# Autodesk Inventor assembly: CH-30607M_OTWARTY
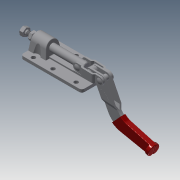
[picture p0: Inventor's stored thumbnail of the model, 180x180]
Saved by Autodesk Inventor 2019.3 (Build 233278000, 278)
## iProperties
Company: Î¢ÈíÖÐ¹ú
Created: 2012-09
Part Number: CH-30607M_OTWARTY
Material: Ogólny
Description: STEP AP203
Document SubType Name: Assembly
Designer: CADENGINEERING4
Sending System: SolidWorks 2010
Preprocessor: SwSTEP 2.0
Title: CH-30607M.STEP
Author: Î¢ÈíÓÃ»§
Revision Number: ÈÎºÎ
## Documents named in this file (10)
- D:\Vault_2016\Projekty\STRONA\Push-pull clamp\CH-30607M\CH-30607M_OTWARTY.iam
- D:\Vault_2016\Projekty\STRONA\Push-pull clamp\CH-30607M\CH-30607-01 BASE.ipt
- D:\Vault_2016\Projekty\STRONA\Push-pull clamp\CH-30607M\M8 Nut.ipt
- D:\Vault_2016\Projekty\STRONA\Push-pull clamp\CH-30607M\CH-SA-085012 SPINDLE SUPPLIED.ipt
- D:\Vault_2016\Projekty\STRONA\Push-pull clamp\CH-30607M\CH-30607-07.ipt
- D:\Vault_2016\Projekty\STRONA\Push-pull clamp\CH-30607M\CH-30607-05.ipt
- D:\Vault_2016\Projekty\STRONA\Push-pull clamp\CH-30607M\CH-30607-04 CONNECTING-PLATE.ipt
- D:\Vault_2016\Projekty\STRONA\Push-pull clamp\CH-30607M\CH-30607-06.ipt
- D:\Vault_2016\Projekty\STRONA\Push-pull clamp\CH-30607M\CH-30607-03 HANDLE.ipt
- D:\Vault_2016\Projekty\STRONA\Push-pull clamp\CH-30607M\CH-30607-02 CREST STALK.ipt
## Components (11 placed, 11 different names)
1. CH-30607-01 BASE_1 — Zestawiające:5, Zestawiające:6, Zestawiające:7, Zestawiające:20, Styczny:1
2. M8 Nut_2 — Zestawiające:1, Zestawiające:2, Zestawiające:3
3. CH-SA-085012 SPINDLE SUPPLIED_3 — Zestawiające:1, Zestawiające:2, Zestawiające:4
4. CH-30607-07_4 — Zestawiające:18, Zestawiające:19
5. CH-30607-05_5 — Zestawiające:9, Równoległe:1, Zestawiające:14, Zestawiające:15
6. CH-30607-04 CONNECTING-PLATE_6 — Zestawiające:11, Zestawiające:12, Zestawiające:13, Zestawiające:14, Zestawiające:16, Zestawiające:17, Zestawiające:19
7. CH-30607-07_7 — Zestawiające:15, Zestawiające:16
8. CH-30607-06_8 — Zestawiające:7, Zestawiające:8
9. CH-30607-04 CONNECTING-PLATE_9 — Zestawiające:10, Zestawiające:12, Zestawiające:13
10. CH-30607-03 HANDLE_10 — Zestawiające:5, Zestawiające:6, Zestawiające:8, Zestawiające:9, Równoległe:1, Zestawiające:10, Zestawiające:11, Styczny:1
11. CH-30607-02 CREST STALK_11 — Zestawiające:3, Zestawiające:4, Zestawiające:17, Zestawiające:18, Zestawiające:20
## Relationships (22: Mate 20, Flush 1, Tangent 1)
- Zestawiające:1 [Mate]: M8 Nut_2 ↔ CH-SA-085012 SPINDLE SUPPLIED_3
- Zestawiające:2 [Mate]: M8 Nut_2 ↔ CH-SA-085012 SPINDLE SUPPLIED_3
- Zestawiające:3 [Mate]: M8 Nut_2 ↔ CH-30607-02 CREST STALK_11
- Zestawiające:4 [Mate]: CH-SA-085012 SPINDLE SUPPLIED_3 ↔ CH-30607-02 CREST STALK_11
- Zestawiające:5 [Mate]: CH-30607-01 BASE_1 ↔ CH-30607-03 HANDLE_10
- Zestawiające:6 [Mate]: CH-30607-01 BASE_1 ↔ CH-30607-03 HANDLE_10
- Zestawiające:7 [Mate]: CH-30607-01 BASE_1 ↔ CH-30607-06_8
- Zestawiające:8 [Mate]: CH-30607-06_8 ↔ CH-30607-03 HANDLE_10
- Zestawiające:9 [Mate]: CH-30607-05_5 ↔ CH-30607-03 HANDLE_10
- Równoległe:1 [Flush]: CH-30607-05_5 ↔ CH-30607-03 HANDLE_10
- Zestawiające:10 [Mate]: CH-30607-04 CONNECTING-PLATE_9 ↔ CH-30607-03 HANDLE_10
- Zestawiające:11 [Mate]: CH-30607-04 CONNECTING-PLATE_6 ↔ CH-30607-03 HANDLE_10
- Zestawiające:12 [Mate]: CH-30607-04 CONNECTING-PLATE_6 ↔ CH-30607-04 CONNECTING-PLATE_9
- Zestawiające:13 [Mate]: CH-30607-04 CONNECTING-PLATE_6 ↔ CH-30607-04 CONNECTING-PLATE_9
- Zestawiające:14 [Mate]: CH-30607-05_5 ↔ CH-30607-04 CONNECTING-PLATE_6
- Zestawiające:15 [Mate]: CH-30607-05_5 ↔ CH-30607-07_7
- Zestawiające:16 [Mate]: CH-30607-04 CONNECTING-PLATE_6 ↔ CH-30607-07_7
- Zestawiające:17 [Mate]: CH-30607-04 CONNECTING-PLATE_6 ↔ CH-30607-02 CREST STALK_11
- Zestawiające:18 [Mate]: CH-30607-07_4 ↔ CH-30607-02 CREST STALK_11
- Zestawiające:19 [Mate]: CH-30607-07_4 ↔ CH-30607-04 CONNECTING-PLATE_6
- Zestawiające:20 [Mate]: CH-30607-01 BASE_1 ↔ CH-30607-02 CREST STALK_11
- Styczny:1 [Tangent]: CH-30607-01 BASE_1 ↔ CH-30607-03 HANDLE_10
